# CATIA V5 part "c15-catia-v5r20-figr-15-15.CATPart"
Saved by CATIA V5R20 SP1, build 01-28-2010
Part number: Part1
Bounding box of the stored display mesh (mm): x -75 to 75, y -66.397 to 33.603, z 0 to 1
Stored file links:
  D:\v5_r20\psrt_files_downloaded\c15\c15-catia-v5r20-figr-15-15.CATPart
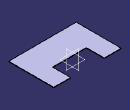
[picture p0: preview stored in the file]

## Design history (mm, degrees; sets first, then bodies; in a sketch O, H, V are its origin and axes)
SheetMetalParameters1: Thickness 1, BendRadius 1, KFactor 0.325257 {= log(min(100,max(20*SheetMetalParameters1.BendRadius,SheetMetalParameters1.Thickness)/SheetMetalParameters1.Thickness))/log(100)/2}, ReliefRadialLength 1, ReliefAxialLength 2, MinimumBendRadius 0
Body1 (main body)
  Sketch1 on xy-plane, origin (0, 0, 0), H (1, 0, 0), V (0, 1, 0)
    line L1 (-37.5, 33.6029) -> (-37.5, -6.3971)
    line L2 (-37.5, -6.3971) -> (37.5, -6.3971)
    line L3 (37.5, -6.3971) -> (37.5, 33.6029)
    line L4 (37.5, 33.6029) -> (75, 33.6029)
    line L5 (75, 33.6029) -> (75, -66.3971)
    line L6 (75, -66.3971) -> (-75, -66.3971)
    line L7 (-75, -66.3971) -> (-75, 33.6029)
    point P8 (-75, 33.6029)
    line L8 (-75, 33.6029) -> (-37.5, 33.6029)
    length L7 = 100
    length L1 = 40
    length L6 = 150
    distance L1 L3 = 75
    vertical: L1 V, L3 V, L5 V, L7 V
    horizontal: L2 H, L4 H, L6 H, L8 H
    coincidence: P8 L4
    symmetry: L7 L5 V, L1 L3 V
  Wall1: Thickness 1, Profile Sketch1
